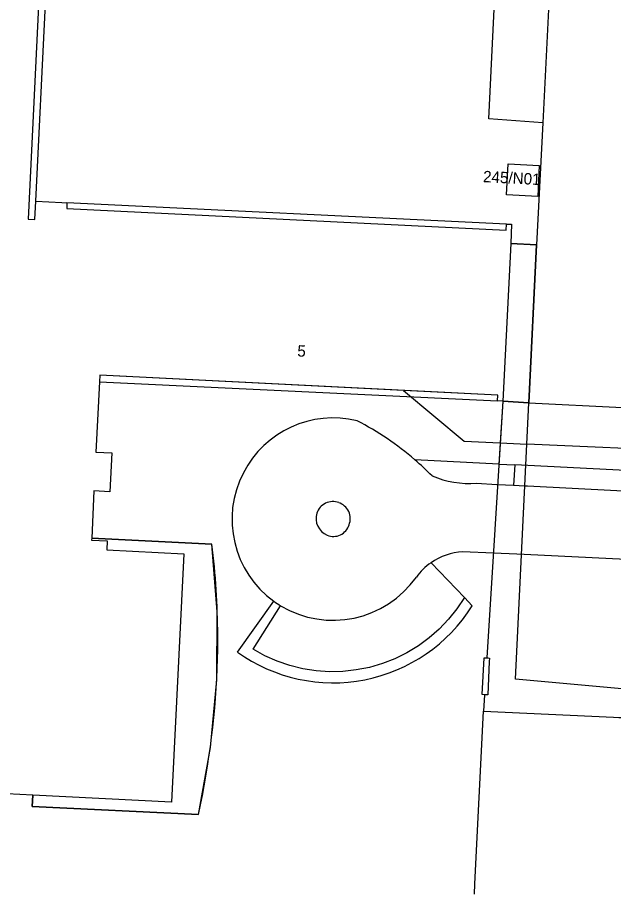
# Model space of a CAD drawing. Extents: x 161761 to 162722, y 384793 to 385405.
# Drawn here: x 162011.7 to 162064.1, y 385249.7 to 385326.1 of the extents above; entities that cross this region are included whole.
import ezdxf

# ---------------------------------------------------------------- set-up
doc = ezdxf.new("R2010")
doc.units = 0
for name, color, linetype in [('IMGEO_Erf', 7, 'Continuous'), ('IMGEO_Muur', 7, 'Continuous'), ('IMGEO_Pand', 7, 'Continuous'), ('IMGEO_Pand_nummerreeks', 7, 'Continuous'), ('IMGEO_Pand_overbouw', 7, 'Continuous'), ('IMGEO_Parkeervlak_open', 7, 'Continuous'), ('IMGEO_Rijbaan_lokaal_gesloten', 7, 'Continuous'), ('IMGEO_Rijbaan_lokaal_open', 7, 'Continuous'), ('IMGEO_Voetpad_open', 7, 'Continuous')]:
    doc.layers.add(name, color=color, linetype=linetype)

msp = doc.modelspace()

# ---------------------------------------------------------------- linework, layer by layer
at = {"layer": 'IMGEO_Erf'}
for points in [[(162045.633, 385293.362), (162050.979, 385288.899), (162054.142, 385288.756)], [(162031.044, 385270.355), (162034.242, 385274.83)], [(162050.992, 385275.146), (162051.687, 385274.418)]]:
    msp.add_lwpolyline(points, dxfattribs=at)
msp.add_arc((162039.45, 385282.117), 14.457, 234.44756, 327.82195, dxfattribs=at)
at = {"layer": 'IMGEO_Muur'}
msp.add_lwpolyline([(162057.875, 385316.893), (162053.132, 385317.221), (162054.39, 385343.133)], dxfattribs=at)
at = {"layer": 'IMGEO_Pand'}
for points in [[(161998.064, 385312.914), (161998.661, 385312.884), (162000, 385339.778), (162000.222, 385344.237), (162014.352, 385343.552), (162012.641, 385308.403), (162013.228, 385308.374), (162013.321, 385310.001), (162015.604, 385309.889), (162016.05, 385309.863), (162016.038, 385309.353), (162054.674, 385307.455), (162054.682, 385307.985), (162055.146, 385307.978), (162055.062, 385306.286)], [(162059.203, 385343.267), (162057.875, 385316.893)], [(162057.875, 385316.893), (162057.335, 385306.161)], [(162057.575, 385313.122), (162057.439, 385310.413), (162054.692, 385310.56), (162054.837, 385313.268), (162057.575, 385313.122)], [(162055.062, 385306.286), (162054.37, 385292.426)], [(162057.335, 385306.161), (162056.667, 385292.277)], [(162056.667, 385292.277), (162089.575, 385290.639), (162089.919, 385297.91), (162088.821, 385297.876), (162088.823, 385297.914)], [(162013.072, 385257.772), (162010.781, 385257.887), (162008.908, 385257.981), (162008.518, 385250.179), (162008.288, 385245.576), (162009.496, 385245.516), (162009.331, 385242.21), (162003.069, 385242.523), (162003.271, 385246.556), (162000, 385246.72), (161996.704, 385246.885), (161996.857, 385250), (161998.226, 385277.953), (161998.388, 385280.863), (161999.086, 385295.276), (161997.176, 385295.369)], [(162045.633, 385293.362), (162018.94, 385294.688), (162018.914, 385294.105), (162018.606, 385287.935), (162019.994, 385287.867), (162019.826, 385284.453), (162018.438, 385284.521), (162018.242, 385280.372)], [(162054.37, 385292.426), (162053.916, 385292.449), (162053.942, 385292.95), (162045.633, 385293.362)], [(162018.242, 385280.372), (162018.234, 385280.198), (162019.609, 385280.14), (162019.578, 385279.344), (162026.337, 385278.987), (162025.247, 385257.16), (162013.072, 385257.772)], [(162053.047, 385266.607), (162052.763, 385266.616), (162052.566, 385266.623), (162052.73, 385269.864), (162053.089, 385269.85), (162053.197, 385269.841), (162053.183, 385269.545), (162053.047, 385266.607)], [(162051.88, 385249.095), (162051.925, 385250), (162052.677, 385265.163), (162064.107, 385264.629)]]:
    msp.add_lwpolyline(points, dxfattribs=at)
msp.add_arc((162065.136, 385283.844), 19.243, 266.93392, 288.19884, dxfattribs=at)
at = {"layer": 'IMGEO_Pand_overbouw'}
for points in [[(161998.064, 385312.914), (161998.661, 385312.884), (162000, 385339.778), (162000.222, 385344.237), (162014.352, 385343.552), (162012.641, 385308.403), (162013.228, 385308.374), (162013.321, 385310.001), (162015.024, 385344.711), (162000, 385345.458), (161999.676, 385345.474)], [(162016.05, 385309.863), (162016.038, 385309.353), (162054.674, 385307.455), (162054.682, 385307.985)], [(162057.335, 385306.161), (162055.062, 385306.286), (162054.37, 385292.426), (162056.667, 385292.277)], [(162053.916, 385292.449), (162053.942, 385292.95), (162018.94, 385294.688), (162018.914, 385294.105)], [(162013.072, 385257.772), (162012.996, 385256.776), (162027.622, 385256.076), (162028.679, 385261.962), (162029.231, 385267.917), (162029.274, 385273.897), (162028.809, 385279.859), (162018.242, 385280.372), (162018.234, 385280.198), (162019.609, 385280.14), (162019.578, 385279.344), (162026.337, 385278.987), (162025.247, 385257.16)]]:
    msp.add_lwpolyline(points, close=True, dxfattribs=at)
for points in [[(162056.667, 385292.277), (162054.37, 385292.426), (162052.968, 385269.855), (162053.089, 385269.85), (162053.197, 385269.841), (162053.183, 385269.543), (162053.047, 385266.607), (162052.767, 385266.616), (162052.677, 385265.163), (162064.107, 385264.629)], [(162071.146, 385265.564), (162071.273, 385266.531), (162055.497, 385267.968), (162056.667, 385292.277)]]:
    msp.add_lwpolyline(points, dxfattribs=at)
msp.add_arc((162065.136, 385283.844), 19.243, 266.93392, 288.19884, dxfattribs=at)
at = {"layer": 'IMGEO_Parkeervlak_open'}
for points in [[(162054.026, 385286.89), (162046.639, 385287.263)], [(162055.428, 385286.819), (162055.318, 385285.029)], [(162048.062, 385278.214), (162050.992, 385275.146)], [(162050.992, 385275.146), (162050.338, 385274.163), (162049.601, 385273.242), (162048.787, 385272.388), (162047.9, 385271.609), (162046.949, 385270.911), (162045.941, 385270.298), (162044.883, 385269.776), (162043.783, 385269.348), (162042.65, 385269.018), (162041.492, 385268.789), (162040.319, 385268.661), (162039.14, 385268.637), (162037.962, 385268.716), (162036.796, 385268.897), (162035.651, 385269.18), (162034.534, 385269.561), (162033.455, 385270.039), (162032.422, 385270.61), (162034.844, 385274.435)]]:
    msp.add_lwpolyline(points, dxfattribs=at)
at = {"layer": 'IMGEO_Rijbaan_lokaal_gesloten'}
msp.add_lwpolyline([(162057.875, 385316.893), (162053.132, 385317.221), (162054.39, 385343.133)], dxfattribs=at)
at = {"layer": 'IMGEO_Rijbaan_lokaal_open'}
for points in [[(162052.057, 385285.194), (162053.849, 385285.103), (162053.915, 385285.1), (162055.318, 385285.029)], [(162055.318, 385285.029), (162056.316, 385284.979), (162056.544, 385284.967), (162096.901, 385282.85)], [(162121.521, 385275.665), (162083.133, 385277.615), (162056.237, 385278.926), (162055.602, 385278.957), (162053.548, 385279.049), (162050.835, 385279.171)]]:
    msp.add_lwpolyline(points, dxfattribs=at)
for centre, radius, start, end in [((162039.477, 385282.029), 8.909, 76.4177, 152.61427), ((162029.557, 385267.449), 26.16, 49.23532, 62.66778), ((162029.253, 385267.116), 26.612, 44.74633, 49.20624), ((162039.459, 385282.031), 8.893, 152.57568, 234.07717), ((162051.471, 385293.653), 8.479, 246.96179, 273.96129), ((162039.428, 385282.095), 1.493, 69.61819, 161.21417), ((162039.509, 385282.106), 1.456, 337.74961, 72.4619), ((162039.559, 385282.118), 1.612, 163.47846, 247.09975), ((162039.48, 385281.959), 1.435, 247.54518, 343.64003), ((162051.158, 385273.74), 5.44, 93.39986, 124.68064), ((162051.176, 385273.729), 5.46, 124.77643, 143.78563), ((162039.451, 385282.117), 8.958, 239.05259, 324.808), ((162039.775, 385282.606), 9.543, 234.56735, 238.89119)]:
    msp.add_arc(centre, radius, start, end, dxfattribs=at)
at = {"layer": 'IMGEO_Voetpad_open'}
for points in [[(162055.062, 385306.286), (162057.335, 385306.161)], [(162088.823, 385297.914), (162090.024, 385298.468), (162090.663, 385298.763), (162090.553, 385296.234), (162090.151, 385287.029), (162089.851, 385287.051), (162090.009, 385289.962), (162083.181, 385290.342), (162083.046, 385287.356), (162071.152, 385287.989), (162056.492, 385288.65)], [(162054.37, 385292.426), (162054.142, 385288.756)], [(162056.667, 385292.277), (162054.37, 385292.426)], [(162056.492, 385288.65), (162056.667, 385292.277)], [(162054.142, 385288.756), (162054.026, 385286.89)], [(162054.142, 385288.756), (162056.492, 385288.65)], [(162054.026, 385286.89), (162055.428, 385286.819)], [(162098.143, 385284.617), (162074.929, 385285.836), (162055.428, 385286.819)], [(162018.242, 385280.372), (162028.809, 385279.859)], [(162027.622, 385256.076), (162012.996, 385256.776), (162013.072, 385257.772)]]:
    msp.add_lwpolyline(points, dxfattribs=at)
for centre, radius, start, end in [((161959.246, 385271.428), 70.072, 0.30886, 6.91025), ((161982.112, 385271.204), 47.209, 358.25711, 0.73083), ((161954.12, 385272.027), 75.213, 347.75566, 358.27869)]:
    msp.add_arc(centre, radius, start, end, dxfattribs=at)

# ---------------------------------------------------------------- texts
at = {"layer": 'IMGEO_Pand_nummerreeks'}
for s, rotation, p in [('245/N01', 357.00907, (162052.614, 385311.671)), ('5', 357.15813, (162036.29, 385296.349))]:
    msp.add_text(s, height=1, rotation=rotation, dxfattribs=at).set_placement(p)

doc.saveas('drawing.dxf')
